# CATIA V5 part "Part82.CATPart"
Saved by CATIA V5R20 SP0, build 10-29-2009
Part number: FA 053000-1
Revision: ANY
Definition: UNKNOWN
Nomenclature: FA 053000-1
Source: Unknown
Bounding box of the stored display mesh (mm): x -1.9 to 1.9, y -1.1 to 2.45, z -1.9 to 1.9
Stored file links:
  C:\Users\Utente\Desktop\IO LAVORO\3D X SITO CF\CUMSA\3D files FA\FA 053012-20\Part82.CATPart

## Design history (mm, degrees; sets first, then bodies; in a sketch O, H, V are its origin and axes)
Body1 "Cortar-Extruir1" (main body)
  Solid1: solid without history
